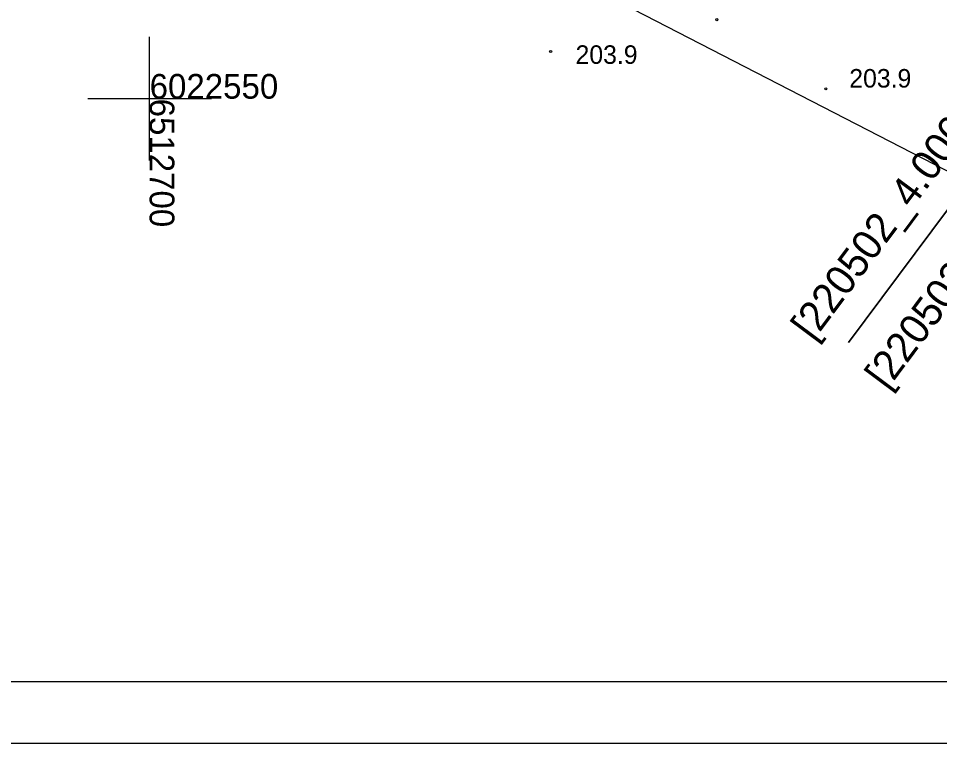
# Model space of a CAD drawing. Extents: x 6512606 to 6513347, y 6022524 to 6022728.
# Drawn here: x 6512694.69 to 6512731.97, y 6022523.88 to 6022553.25 of the extents above; entities that cross this region are included whole.
import ezdxf

# ---------------------------------------------------------------- set-up
doc = ezdxf.new("R2010")
doc.units = 0
for name, color, linetype in [('208-opis obrębu', 7, 'Continuous'), ('216-obręb ewidencyjny', 7, 'Continuous'), ('217-kontur klasyfikacyjny', 7, 'Continuous'), ('218-kontur użytku gruntowego', 7, 'Continuous'), ('219-działka ewidencyjna', 7, 'Continuous'), ('4', 7, 'Continuous'), ('Default', 7, 'Continuous'), ('Komentarz lub etykieta na mapie', 7, 'Continuous'), ('maxp_ramka_2', 7, 'Continuous'), ('Obszar opracowania', 7, 'Continuous'), ('pikieta naturalna', 7, 'Continuous'), ('pikieta naturalna-Atr2', 7, 'Continuous'), ('punkt wysokościowy naturalny', 7, 'Continuous')]:
    doc.layers.add(name, color=color, linetype=linetype)

# ---------------------------------------------------------------- blocks, each defined once
blk = doc.blocks.new('PW01')
at = {"layer": 'Default'}
blk.add_circle((0, 0), 0.45, dxfattribs=at)

msp = doc.modelspace()

# ---------------------------------------------------------------- linework, layer by layer
at = {"layer": '216-obręb ewidencyjny'}
for points in [[(6512728.286, 6022540.131), (6512737.69, 6022552.74), (6512751.08, 6022569.37), (6512775.81, 6022564.08), (6512780.7, 6022581.02), (6512806.2, 6022572.11), (6512806.62, 6022563.51), (6512811.41, 6022558.95), (6512818.47, 6022559.72), (6512828.23, 6022562.62), (6512858.85, 6022571.74), (6512855.78, 6022583.95), (6512853.17, 6022604.51), (6512852.25, 6022608.25), (6512838.47, 6022634.29)], [(6512751.08, 6022569.37), (6512737.69, 6022552.74), (6512728.286, 6022540.131)]]:
    msp.add_lwpolyline(points, dxfattribs=at)
at = {"layer": '217-kontur klasyfikacyjny'}
msp.add_lwpolyline([(6512728.286, 6022540.131), (6512737.69, 6022552.74)], dxfattribs=at)
at = {"layer": '218-kontur użytku gruntowego'}
for points in [[(6512728.286, 6022540.131), (6512737.69, 6022552.74)], [(6512737.69, 6022552.74), (6512728.286, 6022540.131)]]:
    msp.add_lwpolyline(points, dxfattribs=at)
at = {"layer": '219-działka ewidencyjna'}
msp.add_lwpolyline([(6512737.69, 6022552.74), (6512728.286, 6022540.131)], dxfattribs=at)
at = {"layer": '4'}
msp.add_lwpolyline([(6512737.69, 6022552.74), (6512728.286, 6022540.131)], dxfattribs=at)
at = {"layer": 'Default'}
for p, q in [((6512700, 6022547.5), (6512700, 6022552.5)), ((6512697.5, 6022550), (6512702.5, 6022550))]:
    msp.add_line(p, q, dxfattribs=at)
at = {"layer": 'maxp_ramka_2'}
for points in [[(6512605.658, 6022723.882), (6513005.658, 6022723.882), (6513005.658, 6022523.882), (6512605.658, 6022523.882)], [(6512618.158, 6022526.382), (6512618.158, 6022721.382), (6513003.158, 6022721.382), (6513003.158, 6022526.382)]]:
    msp.add_lwpolyline(points, close=True, dxfattribs=at)
at = {"layer": 'Obszar opracowania'}
msp.add_lwpolyline([(6512710.98, 6022693.84), (6512748.35, 6022694.16), (6512798.11, 6022695.25), (6512807.47, 6022695.46), (6512809.66, 6022606.87), (6512863.71, 6022622.03), (6512875.13, 6022581.36), (6512755.22, 6022535.25), (6512691.61, 6022568.03), (6512709.16, 6022605.16)], close=True, dxfattribs=at)

# ---------------------------------------------------------------- block references
at = {"layer": 'pikieta naturalna', "xscale": 0.1, "yscale": 0.10000000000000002}
for p in [(6512716.23, 6022551.91), (6512727.37, 6022550.4)]:
    msp.add_blockref('PW01', p, dxfattribs=at)
at = {"layer": 'punkt wysokościowy naturalny', "xscale": 0.1, "yscale": 0.10000000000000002}
msp.add_blockref('PW01', (6512722.96, 6022553.2), dxfattribs=at)

# ---------------------------------------------------------------- texts
at = {"layer": '208-opis obrębu'}
for s, p in [('[220502_4.0005] 5', (6512726.85, 6022540.15)), ('[220502_4.0005] 6', (6512729.84, 6022538.17))]:
    msp.add_text(s, height=1.2, rotation=53.284, dxfattribs=at).set_placement(p)
at = {"layer": 'Komentarz lub etykieta na mapie'}
msp.add_text('6022550', height=1, dxfattribs=at).set_placement((6512700, 6022550))
msp.add_text('6512700', height=1, rotation=270, dxfattribs=at).set_placement((6512700, 6022550))
at = {"layer": 'pikieta naturalna-Atr2'}
for p in [(6512717.24, 6022551.41), (6512728.32, 6022550.45)]:
    msp.add_text('203.9', height=0.75, dxfattribs=at).set_placement(p)

doc.saveas('drawing.dxf')
